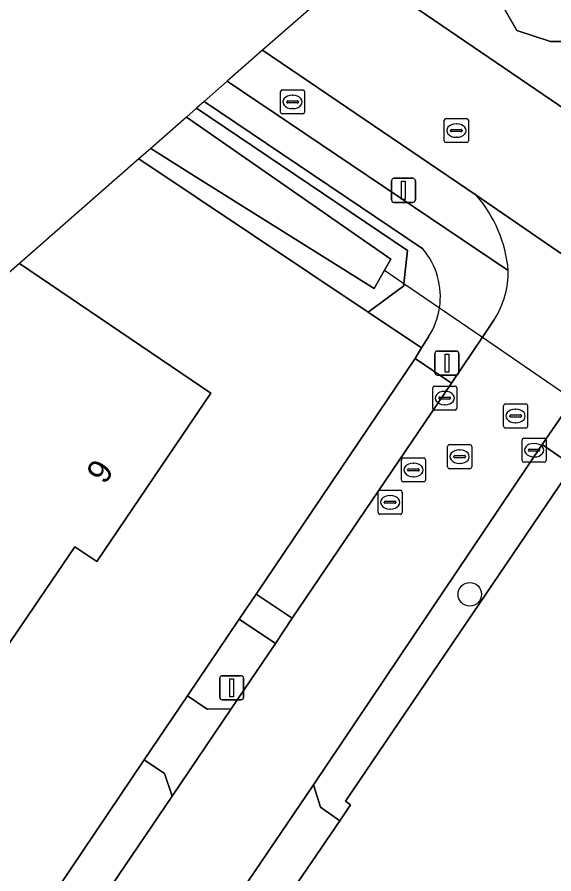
# Model space of a CAD drawing. Extents: x 163859 to 164644, y 379566 to 382155.
# Drawn here: x 164174.78 to 164197.07, y 381831.56 to 381867.17 of the extents above; entities that cross this region are included whole.
import ezdxf

# ---------------------------------------------------------------- set-up
doc = ezdxf.new("R2010")
doc.units = 0
for name, color, linetype in [('IMGEO_Berm_groen', 7, 'Continuous'), ('IMGEO_Boom', 7, 'Continuous'), ('IMGEO_Duiker', 7, 'Continuous'), ('IMGEO_Erf', 7, 'Continuous'), ('IMGEO_Groenvoorziening', 7, 'Continuous'), ('IMGEO_Kolk', 7, 'Continuous'), ('IMGEO_Lichtmast', 7, 'Continuous'), ('IMGEO_Oever', 7, 'Continuous'), ('IMGEO_Pand', 7, 'Continuous'), ('IMGEO_Pand_nummerreeks', 7, 'Continuous'), ('IMGEO_Rijbaan_lokaal_gesloten', 7, 'Continuous'), ('IMGEO_Rijbaan_lokaal_open', 7, 'Continuous'), ('IMGEO_Rioolput', 7, 'Continuous'), ('IMGEO_Voetpad_halfverhard', 7, 'Continuous'), ('IMGEO_Voetpad_open', 7, 'Continuous'), ('IMGEO_Waterloop', 7, 'Continuous')]:
    doc.layers.add(name, color=color, linetype=linetype)

msp = doc.modelspace()

# ---------------------------------------------------------------- linework, layer by layer
at = {"layer": 'IMGEO_Berm_groen'}
for points in [[(164184.975, 381865.791), (164183.51, 381864.507), (164195.178, 381856.64)], [(164193.85, 381859.772), (164184.975, 381865.791)]]:
    msp.add_lwpolyline(points, dxfattribs=at)
msp.add_arc((164189.621, 381856.131), 5.58, 5.2297, 40.7252, dxfattribs=at)
at = {"layer": 'IMGEO_Boom'}
msp.add_circle((164193.579, 381843.182), 0.489, dxfattribs=at)
at = {"layer": 'IMGEO_Duiker'}
msp.add_lwpolyline([(164190.042, 381856.658), (164190.846, 381856.104), (164192.323, 381855.089), (164194.104, 381853.864), (164197.871, 381851.272), (164199.409, 381850.214), (164201.216, 381848.971), (164201.883, 381848.512)], dxfattribs=at)
at = {"layer": 'IMGEO_Erf'}
for points in [[(164172.905, 381825.67), (164176.013, 381830.292), (164180.059, 381836.297), (164181.855, 381838.961), (164183.999, 381842.144), (164184.705, 381843.191), (164191.306, 381852.987), (164191.32, 381853.008), (164191.58, 381853.421), (164189.365, 381854.902), (164179.829, 381861.277), (164174.878, 381856.933)], [(164174.878, 381856.933), (164182.827, 381851.535), (164178.088, 381844.548), (164177.173, 381845.157), (164173.526, 381839.8)], [(164235.043, 381794.138), (164205.955, 381814.209), (164212.364, 381823.54), (164216.274, 381829.253), (164219.843, 381834.466), (164216.141, 381836.213), (164213.566, 381838.056), (164211.492, 381839.541), (164211.311, 381839.272), (164210.023, 381840.13), (164210.234, 381840.441), (164208.977, 381841.341), (164200.437, 381847.454), (164198.212, 381849.047), (164197.859, 381848.521), (164188.424, 381834.578), (164188.626, 381834.431), (164188.179, 381833.768), (164185.088, 381829.228), (164165.885, 381800.687)]]:
    msp.add_lwpolyline(points, dxfattribs=at)
at = {"layer": 'IMGEO_Groenvoorziening'}
for points in [[(164261.825, 381821.183), (164221.968, 381849.023), (164223.061, 381850.617), (164219.769, 381853.023), (164219.553, 381852.482), (164219.129, 381851.953), (164218.468, 381851.741), (164217.304, 381852.35), (164212.541, 381855.181), (164205.239, 381860.42), (164197.592, 381866.161), (164196.931, 381866.161), (164195.529, 381866.611), (164195.052, 381867.457), (164195.268, 381868.391), (164195.29, 381868.489), (164195.394, 381868.583), (164194.945, 381868.909), (164183.031, 381877.576), (164180.902, 381879.968), (164176.8, 381882.795)], [(164175.458, 381878.387), (164203.483, 381859.285), (164205.181, 381858.114), (164214.31, 381851.815), (164215.15, 381853.032), (164227.892, 381844.304), (164227.341, 381843.488), (164229.978, 381841.659), (164230.539, 381842.463), (164236.331, 381838.448), (164235.41, 381837.168), (164242.387, 381832.326), (164242.758, 381832.059), (164272.361, 381810.742), (164289.667, 381798.436), (164312.339, 381782.446)], [(164182.548, 381863.663), (164182.231, 381863.385), (164190.987, 381857.475), (164190.846, 381856.104), (164190.836, 381856.002), (164189.365, 381854.902), (164191.58, 381853.421), (164191.868, 381853.878)], [(164191.631, 381857.534), (164182.548, 381863.663)]]:
    msp.add_lwpolyline(points, dxfattribs=at)
for centre, radius, start, end in [((164189.269, 381855.545), 3.088, 351.5038, 40.1021), ((164189.29, 381855.538), 3.066, 327.2304, 351.5849)]:
    msp.add_arc(centre, radius, start, end, dxfattribs=at)
at = {"layer": 'IMGEO_Kolk'}
for p, q in [((164185.719, 381863.221), (164185.719, 381864.073)), ((164185.794, 381864.147), (164186.646, 381864.147)), ((164186.207, 381863.927), (164186.232, 381863.927)), ((164186.72, 381864.073), (164186.72, 381863.221)), ((164185.978, 381863.641), (164185.978, 381863.653)), ((164186.416, 381863.604), (164186.018, 381863.604)), ((164186.021, 381863.69), (164186.419, 381863.69)), ((164186.462, 381863.653), (164186.462, 381863.641)), ((164186.646, 381863.147), (164185.794, 381863.147)), ((164186.23, 381863.367), (164186.205, 381863.367)), ((164192.04, 381850.909), (164192.04, 381851.761)), ((164192.115, 381851.835), (164192.967, 381851.835)), ((164193.041, 381851.761), (164193.041, 381850.909)), ((164192.528, 381851.615), (164192.553, 381851.615)), ((164192.299, 381851.329), (164192.299, 381851.341)), ((164192.737, 381851.292), (164192.339, 381851.292)), ((164192.342, 381851.378), (164192.74, 381851.378)), ((164192.551, 381851.055), (164192.526, 381851.055)), ((164192.783, 381851.341), (164192.783, 381851.329)), ((164192.967, 381850.835), (164192.115, 381850.835)), ((164195.825, 381849.672), (164196.677, 381849.672)), ((164195.75, 381848.746), (164195.75, 381849.598)), ((164196.238, 381849.452), (164196.263, 381849.452)), ((164196.751, 381849.598), (164196.751, 381848.746)), ((164196.009, 381849.166), (164196.009, 381849.178)), ((164196.447, 381849.129), (164196.049, 381849.129)), ((164196.052, 381849.215), (164196.45, 381849.215)), ((164196.493, 381849.178), (164196.493, 381849.166)), ((164196.677, 381848.672), (164195.825, 381848.672)), ((164196.261, 381848.892), (164196.236, 381848.892))]:
    msp.add_line(p, q, dxfattribs=at)
for points in [[(164185.719, 381863.221), (164185.719, 381864.073)], [(164185.794, 381864.147), (164186.646, 381864.147)], [(164186.72, 381864.073), (164186.72, 381863.221)], [(164186.646, 381863.147), (164185.794, 381863.147)], [(164192.04, 381850.909), (164192.04, 381851.761)], [(164192.115, 381851.835), (164192.967, 381851.835)], [(164193.041, 381851.761), (164193.041, 381850.909)], [(164192.967, 381850.835), (164192.115, 381850.835)], [(164195.825, 381849.672), (164196.677, 381849.672)], [(164195.75, 381848.746), (164195.75, 381849.598)], [(164196.751, 381849.598), (164196.751, 381848.746)], [(164196.677, 381848.672), (164195.825, 381848.672)]]:
    msp.add_lwpolyline(points, dxfattribs=at)
for centre, radius, start, end in [((164185.796, 381864.071), 0.0765, 91.552, 178.448), ((164185.796, 381864.071), 0.0765, 91.552, 178.448), ((164186.644, 381864.071), 0.0765, 1.552, 88.448), ((164186.644, 381864.071), 0.0765, 1.552, 88.448), ((164186.018, 381863.65), 0.0403, 85.8775, 175.7526), ((164186.015, 381863.64), 0.0366, 178.938, 274.7102), ((164186.419, 381863.647), 0.043, 264.8664, 352.4533), ((164186.423, 381863.652), 0.0386, 1.7309, 96.639), ((164185.796, 381863.223), 0.0765, 181.552, 268.448), ((164185.796, 381863.223), 0.0765, 181.552, 268.448), ((164186.644, 381863.223), 0.0765, 271.552, 358.448), ((164186.644, 381863.223), 0.0765, 271.552, 358.448), ((164192.117, 381851.759), 0.0765, 91.552, 178.448), ((164192.117, 381851.759), 0.0765, 91.552, 178.448), ((164192.965, 381851.759), 0.0765, 1.552, 88.448), ((164192.965, 381851.759), 0.0765, 1.552, 88.448), ((164192.339, 381851.338), 0.0403, 85.8775, 175.7526), ((164192.336, 381851.328), 0.0366, 178.938, 274.7102), ((164192.74, 381851.335), 0.043, 264.8664, 352.4533), ((164192.744, 381851.34), 0.0386, 1.7309, 96.639), ((164192.117, 381850.911), 0.0765, 181.552, 268.448), ((164192.117, 381850.911), 0.0765, 181.552, 268.448), ((164192.965, 381850.911), 0.0765, 271.552, 358.448), ((164192.965, 381850.911), 0.0765, 271.552, 358.448), ((164195.827, 381849.596), 0.0765, 91.552, 178.448), ((164195.827, 381849.596), 0.0765, 91.552, 178.448), ((164196.675, 381849.596), 0.0765, 1.552, 88.448), ((164196.675, 381849.596), 0.0765, 1.552, 88.448), ((164196.049, 381849.175), 0.0403, 85.8775, 175.7526), ((164196.046, 381849.165), 0.0366, 178.938, 274.7102), ((164196.45, 381849.172), 0.043, 264.8664, 352.4533), ((164196.454, 381849.177), 0.0386, 1.7309, 96.639), ((164195.827, 381848.748), 0.0765, 181.552, 268.448), ((164195.827, 381848.748), 0.0765, 181.552, 268.448), ((164196.675, 381848.748), 0.0765, 271.552, 358.448), ((164196.675, 381848.748), 0.0765, 271.552, 358.448)]:
    msp.add_arc(centre, radius, start, end, dxfattribs=at)
for centre, major_axis, ratio, start_param, end_param in [((164186.206, 381863.647), (-0.387, 0.002), 0.722429, 4.712389, 7.853982), ((164186.231, 381863.647), (-0.39, 0.002), 0.717154, 1.570796, 4.712389), ((164192.527, 381851.335), (-0.387, 0.002), 0.722429, 4.712389, 7.853982), ((164192.552, 381851.335), (-0.39, 0.002), 0.717154, 1.570796, 4.712389), ((164196.237, 381849.172), (-0.387, 0.002), 0.722429, 4.712389, 7.853982), ((164196.262, 381849.172), (-0.39, 0.002), 0.717154, 1.570796, 4.712389)]:
    msp.add_ellipse(centre, major_axis=major_axis, ratio=ratio, start_param=start_param, end_param=end_param, dxfattribs=at)
at = {"layer": 'IMGEO_Lichtmast'}
for p, q in [((164190.329, 381859.571), (164190.329, 381860.371)), ((164190.329, 381860.371), (164190.329, 381859.571)), ((164190.429, 381860.471), (164191.219, 381860.471)), ((164191.219, 381860.471), (164190.429, 381860.471)), ((164191.319, 381860.371), (164191.319, 381859.571)), ((164191.319, 381859.571), (164191.319, 381860.371)), ((164191.219, 381859.471), (164190.429, 381859.471)), ((164190.429, 381859.471), (164191.219, 381859.471)), ((164192.133, 381852.39), (164192.133, 381853.19)), ((164192.133, 381853.19), (164192.133, 381852.39)), ((164192.233, 381853.29), (164193.023, 381853.29)), ((164193.023, 381853.29), (164192.233, 381853.29)), ((164193.123, 381853.19), (164193.123, 381852.39)), ((164193.123, 381852.39), (164193.123, 381853.19)), ((164193.023, 381852.29), (164192.233, 381852.29)), ((164192.233, 381852.29), (164193.023, 381852.29)), ((164183.193, 381838.897), (164183.193, 381839.697)), ((164183.193, 381839.697), (164183.193, 381838.897)), ((164183.293, 381839.797), (164184.083, 381839.797)), ((164184.083, 381839.797), (164183.293, 381839.797)), ((164184.183, 381839.697), (164184.183, 381838.897)), ((164184.183, 381838.897), (164184.183, 381839.697)), ((164184.083, 381838.797), (164183.293, 381838.797)), ((164183.293, 381838.797), (164184.083, 381838.797))]:
    msp.add_line(p, q, dxfattribs=at)
for points in [[(164190.749, 381860.346), (164190.899, 381860.346), (164190.899, 381859.596), (164190.749, 381859.596), (164190.749, 381860.346)], [(164192.553, 381853.165), (164192.703, 381853.165), (164192.703, 381852.415), (164192.553, 381852.415), (164192.553, 381853.165)], [(164183.613, 381839.672), (164183.763, 381839.672), (164183.763, 381838.922), (164183.613, 381838.922), (164183.613, 381839.672)]]:
    msp.add_lwpolyline(points, dxfattribs=at)
for centre, start, end in [((164190.429, 381860.371), 90, 180), ((164190.429, 381860.371), 90, 180), ((164191.219, 381860.371), 0, 90), ((164191.219, 381860.371), 360, 90), ((164190.429, 381859.571), 180, 270), ((164190.429, 381859.571), 180, 270), ((164191.219, 381859.571), 270, 0), ((164191.219, 381859.571), 270, 0), ((164192.233, 381853.19), 90, 180), ((164192.233, 381853.19), 90, 180), ((164193.023, 381853.19), 0, 90), ((164193.023, 381853.19), 360, 90), ((164192.233, 381852.39), 180, 270), ((164192.233, 381852.39), 180, 270), ((164193.023, 381852.39), 270, 0), ((164193.023, 381852.39), 270, 0), ((164183.293, 381839.697), 90, 180), ((164183.293, 381839.697), 90, 180), ((164184.083, 381839.697), 0, 90), ((164184.083, 381839.697), 360, 90), ((164183.293, 381838.897), 180, 270), ((164183.293, 381838.897), 180, 270), ((164184.083, 381838.897), 270, 0), ((164184.083, 381838.897), 270, 0)]:
    msp.add_arc(centre, 0.1, start, end, dxfattribs=at)
at = {"layer": 'IMGEO_Oever'}
msp.add_lwpolyline([(164181.808, 381863.014), (164190.296, 381857.112), (164190.042, 381856.658), (164189.609, 381855.885), (164182.291, 381860.481), (164180.331, 381861.717), (164180.331, 381861.717), (164179.829, 381861.277), (164189.365, 381854.902), (164190.836, 381856.002), (164190.846, 381856.104), (164190.987, 381857.475), (164182.231, 381863.385), (164181.808, 381863.014)], dxfattribs=at)
at = {"layer": 'IMGEO_Pand'}
msp.add_lwpolyline([(164174.878, 381856.933), (164168.319, 381851.178), (164171.538, 381849.002), (164167.892, 381843.609), (164173.526, 381839.8), (164177.173, 381845.157), (164178.088, 381844.548), (164182.827, 381851.535)], close=True, dxfattribs=at)
at = {"layer": 'IMGEO_Rijbaan_lokaal_gesloten'}
msp.add_lwpolyline([(164184.975, 381865.791), (164193.85, 381859.772), (164202.562, 381853.773), (164205.181, 381858.114), (164203.483, 381859.285), (164175.458, 381878.387), (164175.446, 381878.395), (164166.649, 381884.443), (164166.499, 381884.544), (164143.584, 381899.974), (164141.791, 381898.302), (164187.087, 381867.645)], close=True, dxfattribs=at)
at = {"layer": 'IMGEO_Rijbaan_lokaal_open'}
for points in [[(164202.562, 381853.773), (164193.85, 381859.772)], [(164194.609, 381854.612), (164194.104, 381853.864), (164192.817, 381851.959), (164186.204, 381842.193), (164185.505, 381841.141), (164183.67, 381838.426), (164181.218, 381834.798), (164177.875, 381829.852), (164174.051, 381824.163), (164172.275, 381821.514), (164171.541, 381820.495), (164165.146, 381810.963), (164168.994, 381808.366), (164183.294, 381829.671)], [(164183.294, 381829.671), (164187.087, 381835.261), (164196.592, 381849.406), (164197.871, 381851.272), (164198.396, 381852.037)]]:
    msp.add_lwpolyline(points, dxfattribs=at)
for points in [[(164183.67, 381838.426), (164182.674, 381838.407), (164181.855, 381838.961), (164180.059, 381836.297), (164180.897, 381835.736), (164181.218, 381834.798)], [(164188.179, 381833.768), (164187.373, 381834.333), (164187.087, 381835.261), (164183.294, 381829.671), (164184.248, 381829.772), (164185.088, 381829.228)]]:
    msp.add_lwpolyline(points, close=True, dxfattribs=at)
for centre, radius, start, end in [((164189.621, 381856.131), 5.58, 5.2297, 40.7252), ((164191.427, 381856.599), 3.752, 328.0244, 0.6303)]:
    msp.add_arc(centre, radius, start, end, dxfattribs=at)
at = {"layer": 'IMGEO_Rioolput'}
for p, q in [((164192.521, 381862.03), (164192.521, 381862.882)), ((164192.596, 381862.956), (164193.448, 381862.956)), ((164193.522, 381862.882), (164193.522, 381862.03)), ((164192.78, 381862.45), (164192.78, 381862.462)), ((164192.823, 381862.499), (164193.221, 381862.499)), ((164193.009, 381862.736), (164193.034, 381862.736)), ((164193.264, 381862.462), (164193.264, 381862.45)), ((164193.218, 381862.413), (164192.82, 381862.413)), ((164193.032, 381862.176), (164193.007, 381862.176)), ((164193.448, 381861.956), (164192.596, 381861.956)), ((164195.057, 381851.093), (164195.909, 381851.093)), ((164194.982, 381850.167), (164194.982, 381851.019)), ((164195.47, 381850.873), (164195.495, 381850.873)), ((164195.983, 381851.019), (164195.983, 381850.167)), ((164195.241, 381850.587), (164195.241, 381850.599)), ((164195.679, 381850.55), (164195.281, 381850.55)), ((164195.284, 381850.636), (164195.682, 381850.636)), ((164195.725, 381850.599), (164195.725, 381850.587)), ((164195.909, 381850.093), (164195.057, 381850.093)), ((164195.493, 381850.313), (164195.468, 381850.313)), ((164192.657, 381848.477), (164192.657, 381849.329)), ((164192.732, 381849.403), (164193.584, 381849.403)), ((164193.658, 381849.329), (164193.658, 381848.477)), ((164192.916, 381848.897), (164192.916, 381848.909)), ((164192.959, 381848.946), (164193.357, 381848.946)), ((164193.145, 381849.183), (164193.17, 381849.183)), ((164193.4, 381848.909), (164193.4, 381848.897)), ((164190.74, 381847.924), (164190.74, 381848.776)), ((164190.815, 381848.85), (164191.667, 381848.85)), ((164191.228, 381848.63), (164191.253, 381848.63)), ((164191.741, 381848.776), (164191.741, 381847.924)), ((164193.354, 381848.86), (164192.956, 381848.86)), ((164193.168, 381848.623), (164193.143, 381848.623)), ((164190.999, 381848.344), (164190.999, 381848.356)), ((164191.437, 381848.307), (164191.039, 381848.307)), ((164191.042, 381848.393), (164191.44, 381848.393)), ((164191.483, 381848.356), (164191.483, 381848.344)), ((164193.584, 381848.403), (164192.732, 381848.403)), ((164191.667, 381847.85), (164190.815, 381847.85)), ((164191.251, 381848.07), (164191.226, 381848.07)), ((164189.845, 381847.506), (164190.697, 381847.506)), ((164189.77, 381846.58), (164189.77, 381847.432)), ((164190.258, 381847.286), (164190.283, 381847.286)), ((164190.771, 381847.432), (164190.771, 381846.58)), ((164190.029, 381847), (164190.029, 381847.012)), ((164190.467, 381846.963), (164190.069, 381846.963)), ((164190.072, 381847.049), (164190.47, 381847.049)), ((164190.513, 381847.012), (164190.513, 381847)), ((164190.697, 381846.506), (164189.845, 381846.506)), ((164190.281, 381846.726), (164190.256, 381846.726))]:
    msp.add_line(p, q, dxfattribs=at)
for points in [[(164192.521, 381862.03), (164192.521, 381862.882)], [(164192.596, 381862.956), (164193.448, 381862.956)], [(164193.522, 381862.882), (164193.522, 381862.03)], [(164193.448, 381861.956), (164192.596, 381861.956)], [(164195.057, 381851.093), (164195.909, 381851.093)], [(164194.982, 381850.167), (164194.982, 381851.019)], [(164195.983, 381851.019), (164195.983, 381850.167)], [(164195.909, 381850.093), (164195.057, 381850.093)], [(164192.657, 381848.477), (164192.657, 381849.329)], [(164192.732, 381849.403), (164193.584, 381849.403)], [(164193.658, 381849.329), (164193.658, 381848.477)], [(164190.74, 381847.924), (164190.74, 381848.776)], [(164190.815, 381848.85), (164191.667, 381848.85)], [(164191.741, 381848.776), (164191.741, 381847.924)], [(164193.584, 381848.403), (164192.732, 381848.403)], [(164191.667, 381847.85), (164190.815, 381847.85)], [(164189.845, 381847.506), (164190.697, 381847.506)], [(164189.77, 381846.58), (164189.77, 381847.432)], [(164190.771, 381847.432), (164190.771, 381846.58)], [(164190.697, 381846.506), (164189.845, 381846.506)]]:
    msp.add_lwpolyline(points, dxfattribs=at)
for centre, radius, start, end in [((164192.598, 381862.88), 0.0765, 91.552, 178.448), ((164192.598, 381862.88), 0.0765, 91.552, 178.448), ((164193.446, 381862.88), 0.0765, 1.552, 88.448), ((164193.446, 381862.88), 0.0765, 1.552, 88.448), ((164192.82, 381862.459), 0.0403, 85.8775, 175.7526), ((164192.817, 381862.449), 0.0366, 178.938, 274.7102), ((164193.221, 381862.456), 0.043, 264.8664, 352.4533), ((164193.225, 381862.461), 0.0386, 1.7309, 96.639), ((164192.598, 381862.032), 0.0765, 181.552, 268.448), ((164192.598, 381862.032), 0.0765, 181.552, 268.448), ((164193.446, 381862.032), 0.0765, 271.552, 358.448), ((164193.446, 381862.032), 0.0765, 271.552, 358.448), ((164195.059, 381851.017), 0.0765, 91.552, 178.448), ((164195.059, 381851.017), 0.0765, 91.552, 178.448), ((164195.907, 381851.017), 0.0765, 1.552, 88.448), ((164195.907, 381851.017), 0.0765, 1.552, 88.448), ((164195.281, 381850.596), 0.0403, 85.8775, 175.7526), ((164195.278, 381850.586), 0.0366, 178.938, 274.7102), ((164195.682, 381850.593), 0.043, 264.8664, 352.4533), ((164195.686, 381850.598), 0.0386, 1.7309, 96.639), ((164195.059, 381850.169), 0.0765, 181.552, 268.448), ((164195.059, 381850.169), 0.0765, 181.552, 268.448), ((164195.907, 381850.169), 0.0765, 271.552, 358.448), ((164195.907, 381850.169), 0.0765, 271.552, 358.448), ((164192.734, 381849.327), 0.0765, 91.552, 178.448), ((164192.734, 381849.327), 0.0765, 91.552, 178.448), ((164193.582, 381849.327), 0.0765, 1.552, 88.448), ((164193.582, 381849.327), 0.0765, 1.552, 88.448), ((164192.956, 381848.906), 0.0403, 85.8775, 175.7526), ((164192.953, 381848.896), 0.0366, 178.938, 274.7102), ((164193.357, 381848.903), 0.043, 264.8664, 352.4533), ((164193.361, 381848.908), 0.0386, 1.7309, 96.639), ((164190.817, 381848.774), 0.0765, 91.552, 178.448), ((164190.817, 381848.774), 0.0765, 91.552, 178.448), ((164191.665, 381848.774), 0.0765, 1.552, 88.448), ((164191.665, 381848.774), 0.0765, 1.552, 88.448), ((164191.039, 381848.353), 0.0403, 85.8775, 175.7526), ((164191.036, 381848.343), 0.0366, 178.938, 274.7102), ((164191.44, 381848.35), 0.043, 264.8664, 352.4533), ((164191.444, 381848.355), 0.0386, 1.7309, 96.639), ((164192.734, 381848.479), 0.0765, 181.552, 268.448), ((164192.734, 381848.479), 0.0765, 181.552, 268.448), ((164193.582, 381848.479), 0.0765, 271.552, 358.448), ((164193.582, 381848.479), 0.0765, 271.552, 358.448), ((164190.817, 381847.926), 0.0765, 181.552, 268.448), ((164190.817, 381847.926), 0.0765, 181.552, 268.448), ((164191.665, 381847.926), 0.0765, 271.552, 358.448), ((164191.665, 381847.926), 0.0765, 271.552, 358.448), ((164189.847, 381847.43), 0.0765, 91.552, 178.448), ((164189.847, 381847.43), 0.0765, 91.552, 178.448), ((164190.695, 381847.43), 0.0765, 1.552, 88.448), ((164190.695, 381847.43), 0.0765, 1.552, 88.448), ((164190.069, 381847.009), 0.0403, 85.8775, 175.7526), ((164190.066, 381846.999), 0.0366, 178.938, 274.7102), ((164190.47, 381847.006), 0.043, 264.8664, 352.4533), ((164190.474, 381847.011), 0.0386, 1.7309, 96.639), ((164189.847, 381846.582), 0.0765, 181.552, 268.448), ((164189.847, 381846.582), 0.0765, 181.552, 268.448), ((164190.695, 381846.582), 0.0765, 271.552, 358.448), ((164190.695, 381846.582), 0.0765, 271.552, 358.448)]:
    msp.add_arc(centre, radius, start, end, dxfattribs=at)
for centre, major_axis, ratio, start_param, end_param in [((164193.008, 381862.456), (-0.387, 0.002), 0.722429, 4.712389, 7.853982), ((164193.033, 381862.456), (-0.39, 0.002), 0.717154, 1.570796, 4.712389), ((164195.469, 381850.593), (-0.387, 0.002), 0.722429, 4.712389, 7.853982), ((164195.494, 381850.593), (-0.39, 0.002), 0.717154, 1.570796, 4.712389), ((164193.144, 381848.903), (-0.387, 0.002), 0.722429, 4.712389, 7.853982), ((164193.169, 381848.903), (-0.39, 0.002), 0.717154, 1.570796, 4.712389), ((164191.227, 381848.35), (-0.387, 0.002), 0.722429, 4.712389, 7.853982), ((164191.252, 381848.35), (-0.39, 0.002), 0.717154, 1.570796, 4.712389), ((164190.257, 381847.006), (-0.387, 0.002), 0.722429, 4.712389, 7.853982), ((164190.282, 381847.006), (-0.39, 0.002), 0.717154, 1.570796, 4.712389)]:
    msp.add_ellipse(centre, major_axis=major_axis, ratio=ratio, start_param=start_param, end_param=end_param, dxfattribs=at)
at = {"layer": 'IMGEO_Voetpad_halfverhard'}
for points in [[(164192.817, 381851.959), (164191.306, 381852.987), (164184.705, 381843.191), (164186.204, 381842.193)], [(164197.859, 381848.521), (164196.592, 381849.406), (164187.087, 381835.261), (164187.373, 381834.333), (164188.179, 381833.768), (164188.626, 381834.431), (164188.424, 381834.578)], [(164185.505, 381841.141), (164183.999, 381842.144), (164181.855, 381838.961), (164182.674, 381838.407), (164183.67, 381838.426)], [(164181.218, 381834.798), (164180.897, 381835.736), (164180.059, 381836.297), (164176.013, 381830.292), (164176.867, 381829.747), (164177.875, 381829.852)]]:
    msp.add_lwpolyline(points, close=True, dxfattribs=at)
at = {"layer": 'IMGEO_Voetpad_open'}
for points in [[(164183.51, 381864.507), (164182.548, 381863.663), (164191.631, 381857.534)], [(164195.178, 381856.64), (164183.51, 381864.507)], [(164191.868, 381853.878), (164191.58, 381853.421), (164191.32, 381853.008), (164191.306, 381852.987), (164192.817, 381851.959), (164194.104, 381853.864), (164194.609, 381854.612)], [(164198.396, 381852.037), (164197.871, 381851.272), (164196.592, 381849.406), (164197.859, 381848.521), (164198.212, 381849.047), (164198.432, 381849.375)]]:
    msp.add_lwpolyline(points, dxfattribs=at)
msp.add_lwpolyline([(164184.705, 381843.191), (164183.999, 381842.144), (164185.505, 381841.141), (164186.204, 381842.193)], close=True, dxfattribs=at)
for centre, radius, start, end in [((164189.269, 381855.545), 3.088, 351.5038, 40.1021), ((164191.427, 381856.599), 3.752, 328.0244, 0.6303), ((164189.29, 381855.538), 3.066, 327.2304, 351.5849)]:
    msp.add_arc(centre, radius, start, end, dxfattribs=at)
at = {"layer": 'IMGEO_Waterloop'}
for points in [[(164195.052, 381867.457), (164195.529, 381866.611), (164196.931, 381866.161), (164197.592, 381866.161), (164205.239, 381860.42), (164212.541, 381855.181), (164217.304, 381852.35), (164218.468, 381851.741), (164219.129, 381851.953), (164219.553, 381852.482), (164219.769, 381853.023), (164219.743, 381853.042), (164212.773, 381858.254), (164203.607, 381864.729), (164200.241, 381867.209)], [(164181.808, 381863.014), (164180.331, 381861.717), (164180.331, 381861.717), (164182.291, 381860.481), (164189.609, 381855.885), (164190.042, 381856.658), (164190.296, 381857.112), (164181.808, 381863.014)]]:
    msp.add_lwpolyline(points, dxfattribs=at)

# ---------------------------------------------------------------- texts
at = {"layer": 'IMGEO_Pand_nummerreeks'}
msp.add_text('9', height=1, rotation=55.8519, dxfattribs=at).set_placement((164178.42, 381847.709))

doc.saveas('drawing.dxf')
